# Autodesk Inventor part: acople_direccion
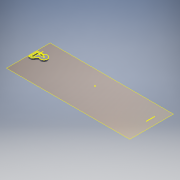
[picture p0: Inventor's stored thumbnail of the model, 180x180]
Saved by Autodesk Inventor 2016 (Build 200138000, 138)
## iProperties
Created: 2017-06
Part Number: acople_direccion
Material: Generic
Document SubType Name: Modeling
Designer: laboratorioesan
Density: 1 g/cm^3
Appearance: Default
Author: laboratorioesan
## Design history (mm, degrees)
workplane "Work Plane1"
sketch "Sketch1"
  geometry: L1 (-120, 104.183)-(-120, 85.683) reference; L2 (-120, 85.683)-(-180, 85.683) reference; L3 (-180, 85.683)-(-180, 104.183) reference; L4 (-180, 104.183)-(-120, 104.183) reference; L5 (370, 85.683)-(370, 104.183) reference; L6 (370, 104.183)-(430, 104.183) reference; L7 (430, 104.183)-(430, 85.683) reference; L8 (430, 85.683)-(370, 85.683) reference; L9 (180, 104.183)-(180, 85.683) reference; L10 (180, 85.683)-(120, 85.683) reference; L11 (120, 85.683)-(120, 104.183) reference; L12 (120, 104.183)-(180, 104.183) reference; L13 (-370, 104.183)-(-370, 85.683) reference; L14 (-370, 85.683)-(-430, 85.683) reference; L15 (-430, 85.683)-(-430, 104.183) reference; L16 (-430, 104.183)-(-370, 104.183) reference; L17 (448.5, -177.817)-(448.5, -117.817) reference; L18 (448.5, -117.817)-(467, -117.817) reference; L19 (467, -117.817)-(467, -177.817) reference; L20 (467, -177.817)-(448.5, -177.817) reference; L21 (-467, -177.817)-(-467, -117.817) reference; L22 (-467, -117.817)-(-448.5, -117.817) reference; L23 (-448.5, -117.817)-(-448.5, -177.817) reference; L24 (-448.5, -177.817)-(-467, -177.817) reference; L25 (400, 37.183)-(400, 55.683) reference; L26 (400, 55.683)-(460, 55.683) reference; L27 (460, 55.683)-(460, 37.183) reference; L28 (460, 37.183)-(400, 37.183) reference; L29 (190, 37.183)-(190, 55.683) reference; L30 (190, 55.683)-(250, 55.683) reference; L31 (250, 55.683)-(250, 37.183) reference; L32 (250, 37.183)-(190, 37.183) reference; L33 (-30, 37.183)-(-30, 55.683) reference; L34 (-30, 55.683)-(30, 55.683) reference; L35 (30, 55.683)-(30, 37.183) reference; L36 (30, 37.183)-(-30, 37.183) reference; L37 (-460, 37.183)-(-460, 55.683) reference; L38 (-460, 55.683)-(-400, 55.683) reference; L39 (-400, 55.683)-(-400, 37.183) reference; L40 (-400, 37.183)-(-460, 37.183) reference; L41 (-250, 37.183)-(-250, 55.683) reference; L42 (-250, 55.683)-(-190, 55.683) reference; L43 (-190, 55.683)-(-190, 37.183) reference; L44 (-190, 37.183)-(-250, 37.183) reference; L45 (-477.824, 115.072)-(-530, 37.183) reference; L46 (-530, 37.183)-(-530, -47.503) reference; L47 (-530, -47.503)-(-485.998, -191.117) reference; L48 (-428.63, -233.54)-(-370, -233.54) reference; L49 (-370, -233.54)-(-370, -52.817) reference; L50 (-310, 7.183)-(310, 7.183) reference; L51 (370, -52.817)-(370, -233.54) reference; L52 (370, -233.54)-(428.63, -233.54) reference; L53 (485.998, -191.117)-(530, -47.503) reference; L54 (530, -47.503)-(530, 37.183) reference; L55 (530, 37.183)-(477.824, 115.072) reference; L56 (427.975, 141.679)-(-427.975, 141.679) reference; L57 (-470, 37.183)-(-495, 55.683) reference; L58 (-460, 37.183)-(-470, 37.183) reference; L59 (-448.5, -92.817)-(-467, -92.817) reference; L60 (-505.617, 17.183)-(-560, 17.183); L61 (-560, 17.183)-(-560, -22.817); L62 (-558.781, 46.433)-(-560, 46.433); L63 (-560, 17.183)-(-560, -67.817); L64 (-560, -67.817)-(-530, -67.817)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; C1 r 5.25 at (-480, -2.817) reference; C2 r 5.25 at (480, -2.817) reference; A1 r 60 centre (-427.975, 81.679) between (-427.975, 141.679) and (-477.824, 115.072) reference; A2 r 60 centre (-428.63, -173.54) between (-485.998, -191.117) and (-428.63, -233.54) reference; A3 r 60 centre (-310, -52.817) between (-310, 7.183) and (-370, -52.817) reference; A4 r 60 centre (310, -52.817) between (370, -52.817) and (310, 7.183) reference; A5 r 60 centre (428.63, -173.54) between (428.63, -233.54) and (485.998, -191.117) reference; A6 r 60 centre (427.975, 81.679) between (477.824, 115.072) and (427.975, 141.679) reference; A7 r 32.5 centre (-480, -2.817) between (-499.816, -28.578) and (-505.617, 17.183); 3 further points
  constraints: 28 end point, 5 parallel, 4 horizontal, 4 perpendicular, 3 point on circle, 1 centre point, 1 coincident, 1 horizontal alignment, 1 midpoint, 1 point on line
  dimensions: "d0" = 65 diameter of A7; "d1" = 40 distance of L60.end L61.end; "d2" = 30 distance from line of L60.end L46; "d3" = 30 distance of L63.end L64.end; "d11" = 18.5 distance of L68.end L69.end; "d12" = 60 distance of L67.end L68.end; "d13" = 10 distance between parallel lines of L63 L68; "d14" = 12.5 distance between parallel lines of L64 L67; "d15" = 25 distance of L72.end L73.end; "d16" = 18.5 distance of L71.end L72.end; "d17" = 10 distance between parallel lines of L70 L72
extrude "Extrusion2" new body sketch "Sketch1" distance "d18" = 18.5; taper "d19" = 0 deg
sketch "Sketch2"
  geometry: L1 (-550, -55.317)-(-550, 4.683) reference; L2 (-530, 37.183)-(-530, -47.503) reference; L3 (530, -47.503)-(530, 37.183) reference; L4 (-530, 37.183)-(-530, -47.503) reference; 1 further point
  node "Reference6"
  node "Reference7"
  node "Reference8"
  node "Reference9"
sketch "Sketch3"
  geometry: L1 (-550, 4.683)-(-550, -55.317) reference; L2 (-550, -55.317)-(-531.5, -55.317) reference; L3 (-531.5, -55.317)-(-531.5, 4.683) reference; L4 (-531.5, 4.683)-(-550, 4.683) reference; L5 (-521.5, 11.521)-(-521.5, -6.979) reference; L6 (-521.5, -6.979)-(-496.5, -6.979) reference; L7 (-496.5, -6.979)-(-496.5, 11.521) reference; L8 (-496.5, 11.521)-(-521.5, 11.521) reference; L9 (-560, -67.817)-(-560, 17.183) reference; L10 (-560, 17.183)-(-505.617, 17.183) reference; L11 (-499.816, -28.578)-(-530, -67.817) reference; L12 (-530, -67.817)-(-560, -67.817) reference; C1 r 5.25 at (-480, -2.817) reference; A1 r 32.5 centre (-480, -2.817) between (-499.816, -28.578) and (-505.617, 17.183) reference; 1 further point
  node "Projected Loop1"
body "Solid2"
node "Reference1"
node "Reference2"
node "Reference3"
node "Reference4"
node "Reference5"
